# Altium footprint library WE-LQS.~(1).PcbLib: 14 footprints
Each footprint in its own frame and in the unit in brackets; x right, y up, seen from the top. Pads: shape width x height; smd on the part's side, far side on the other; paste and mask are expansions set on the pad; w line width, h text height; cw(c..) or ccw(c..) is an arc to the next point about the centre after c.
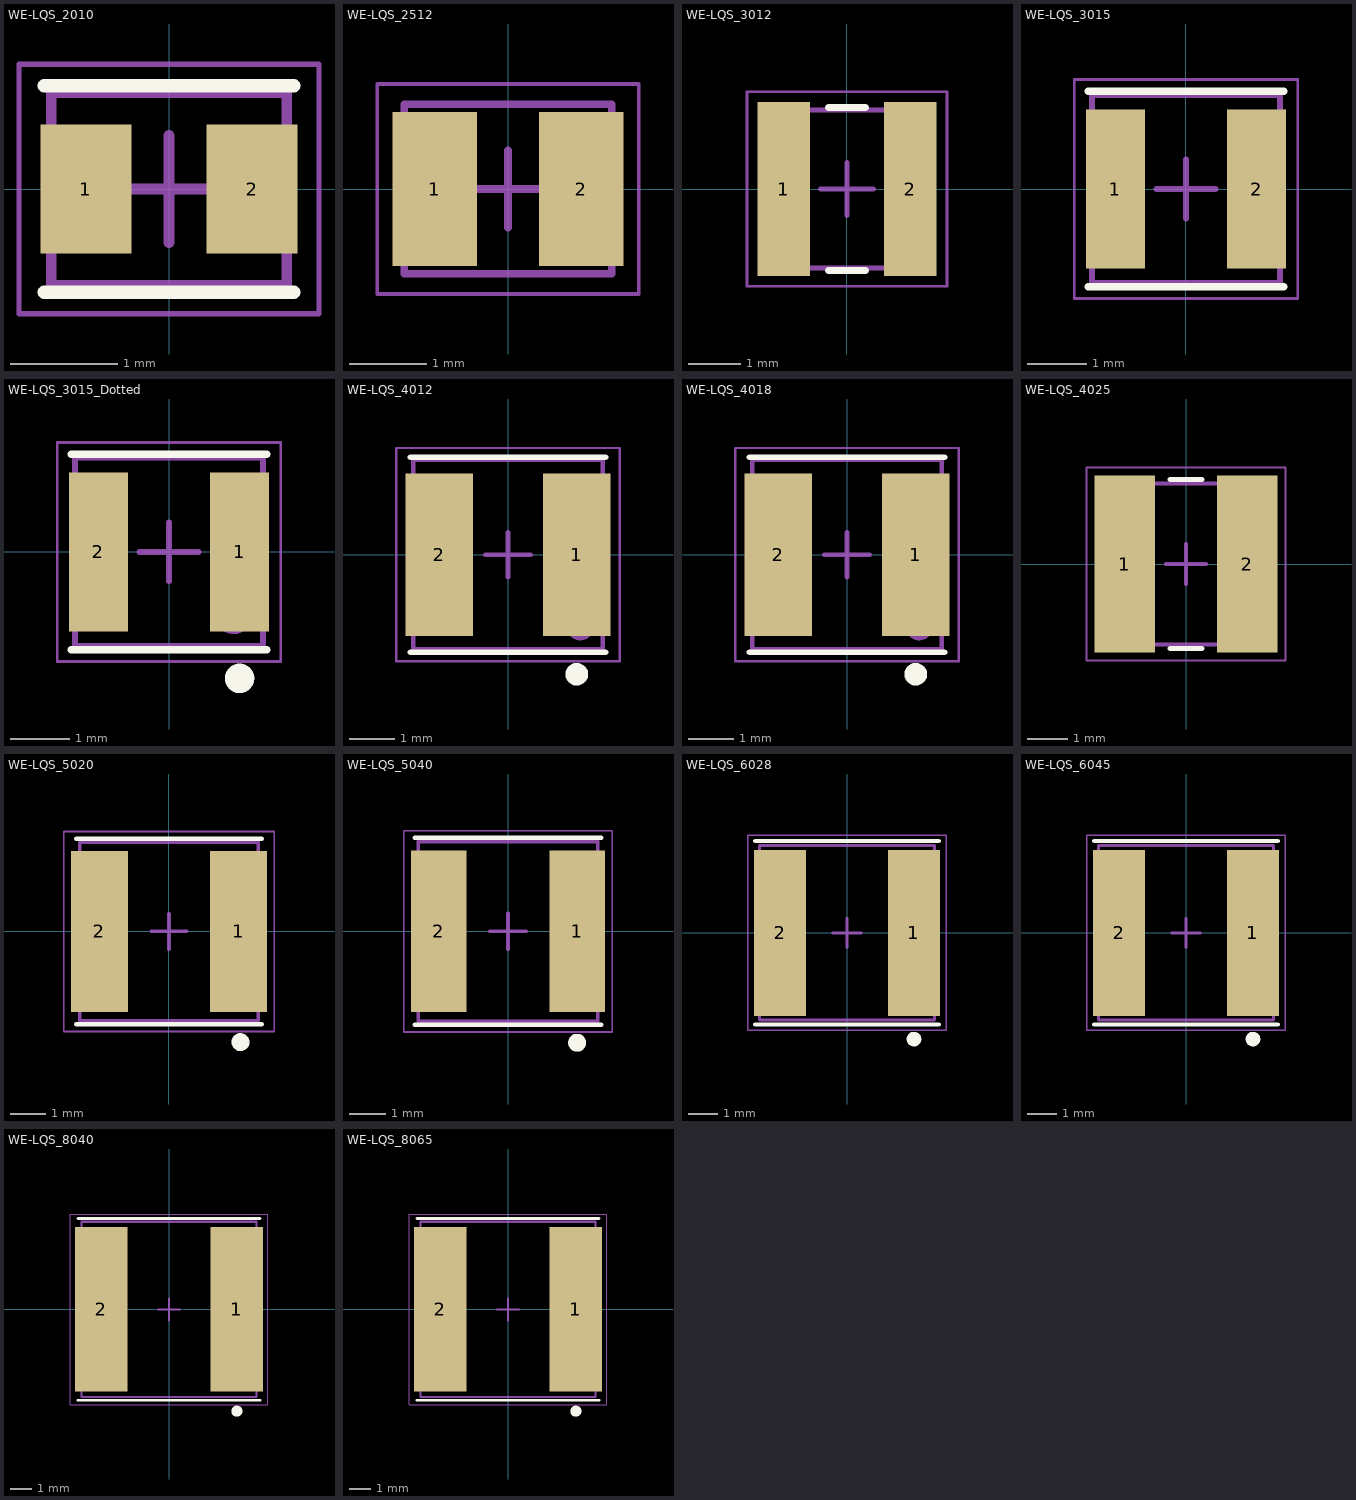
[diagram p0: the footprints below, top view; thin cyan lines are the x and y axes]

## WE-LQS_2010 [mm] "SMD Power Inductor, 2-Leads, body 2x1.6mm"
height 1
pads (2):
  rect 0.85x1.2 smd: 1(-0.775,0) 2(0.775,0)
Top Overlay:
  lines w0.127: -1.164,-0.964 1.164,-0.964 ; -1.164,0.964 1.164,0.964
Top Assembly:
  lines w0.1: -1.1,-0.9 1.1,-0.9 1.1,0.9 -1.1,0.9 -1.1,-0.9
Top Designator:
  text ".Designator" at -3.647,-0.357 h1
Top Courtyard:
  lines w0.05: -1.4,-1.164 1.4,-1.164 1.4,1.164 -1.4,1.164 -1.4,-1.164
Top Component Center:
  lines w0.1: -0.5,0 0.5,0 ; 0,-0.5 0,0.5
3D body "IndLQS_2010.stp": height 1.01, standoff 0.01, extent -1,-0.8 1,0.824

## WE-LQS_2512 [mm] "SMD Power Inductor, 2-Leads, body 2.5x2mm"
height 1.2
pads (2):
  rect 1.1x2 smd: 1(-0.95,0) 2(0.95,0)
Top Assembly:
  lines w0.1: -1.35,-1.1 -1.35,1.1 1.35,1.1 1.35,-1.1 -1.35,-1.1
Top Designator:
  text ".Designator" at -3.647,-0.357 h1
Top Courtyard:
  lines w0.05: -1.7,-1.363 1.7,-1.363 1.7,1.363 -1.7,1.363 -1.7,-1.363
Top Component Center:
  lines w0.1: -0.5,0 0.5,0 ; 0,-0.5 0,0.5
3D body "IndLQS_2512.stp": height 1.2, standoff 0, extent -1.25,-1 1.25,1

## WE-LQS_3012 [mm] "SMD Power Inductor, 2-Leads, body 3x3mm"
height 1.2
pads (2):
  rect 1x3.3 smd: 1(-1.2,0) 2(1.2,0)
Top Overlay:
  lines w0.127: -0.35,-1.55 0.35,-1.55 ; -0.35,1.55 0.35,1.55
Top Assembly:
  lines w0.1: -1.5,-1.5 1.5,-1.5 1.5,1.5 -1.5,1.5 -1.5,-1.5
Top Designator:
  text ".Designator" at -3.647,-0.357 h1
Top Courtyard:
  lines w0.05: -1.9,-1.85 -1.9,1.85 1.9,1.85 1.9,-1.85 -1.9,-1.85
Top Component Center:
  lines w0.1: -0.5,0 0.5,0 ; 0,-0.5 0,0.5
3D body "IndLQS_3012_TPI_74404031xxxA.stp": height 1.2, standoff 0, extent -1.5,-1.5 1.5,1.5

## WE-LQS_3015 [mm] "SMD Power Inductor, 2-Leads, body 3x3mm"
height 1.5
pads (2):
  rect 1x2.7 smd: 1(-1.2,0) 2(1.2,0)
Top Overlay:
  lines w0.127: -1.663,-1.663 1.663,-1.663 ; -1.663,1.663 1.663,1.663
Top Assembly:
  lines w0.1: -1.6,-1.6 1.6,-1.6 1.6,1.6 -1.6,1.6 -1.6,-1.6
Top Designator:
  text ".Designator" at -3.647,-0.357 h1
Top Courtyard:
  lines w0.05: -1.9,-1.863 -1.9,1.863 1.9,1.863 1.9,-1.863 -1.9,-1.863
Top Component Center:
  lines w0.1: -0.5,0 0.5,0 ; 0,-0.5 0,0.5
3D body "LQS_3015.stp": height 1.5, standoff 0, extent -1.5,-1.5 1.5,1.5

## WE-LQS_3015_Dotted [mm] "SMD Power Inductor, 2-Leads, body 3x3mm"
height 1.5
pads (2):
  rect 1x2.7 smd: 1(1.2,0) 2(-1.2,0)
Top Overlay:
  circle w0.25: c1.2,-2.15 r0.125
  lines w0.127: -1.663,-1.663 1.663,-1.663 ; -1.663,1.663 1.663,1.663
Top Assembly:
  circle w0.1: c1.1,-1.1 r0.25
  lines w0.1: -1.6,-1.6 -1.6,1.6 1.6,1.6 1.6,-1.6 -1.6,-1.6
Top Designator:
  text ".Designator" at -3.647,-0.357 h1
Top Courtyard:
  lines w0.05: -1.9,-1.863 1.9,-1.863 1.9,1.863 -1.9,1.863 -1.9,-1.863
Top Component Center:
  lines w0.1: -0.5,0 0.5,0 ; 0,-0.5 0,0.5
3D body "IndLQS_3015_74404032220.stp": height 1.45, standoff -0.01, extent -1.5,-1.5 1.5,1.5

## WE-LQS_4012 [mm] "SMD Power Inductor, 2-Leads, body 4x4mm"
height 1.2
pads (2):
  rect 1.5x3.6 smd: 1(1.525,0) 2(-1.525,0)
Top Overlay:
  circle w0.25: c1.525,-2.65 r0.125
  lines w0.127: -2.164,-2.164 2.164,-2.164 ; -2.164,2.164 2.164,2.164
Top Assembly:
  circle w0.1: c1.6,-1.6 r0.25
  lines w0.1: -2.1,-2.1 2.1,-2.1 2.1,2.1 -2.1,2.1 -2.1,-2.1
Top Designator:
  text ".Designator" at -3.647,-0.357 h1
Top Courtyard:
  lines w0.05: -2.475,-2.364 -2.475,2.364 2.475,2.364 2.475,-2.364 -2.475,-2.364
Top Component Center:
  lines w0.1: -0.5,0 0.5,0 ; 0,-0.5 0,0.5
3D body "IndLQS_4012.stp": height 1.19, standoff -0.01, extent -2,-2 2,2

## WE-LQS_4018 [mm] "SMD Power Inductor, 2-Leads, body 4x4mm"
height 1.8
pads (2):
  rect 1.5x3.6 smd: 1(1.525,0) 2(-1.525,0)
Top Overlay:
  circle w0.25: c1.525,-2.65 r0.125
  lines w0.127: -2.164,-2.164 2.164,-2.164 ; -2.164,2.164 2.164,2.164
Top Assembly:
  circle w0.1: c1.6,-1.6 r0.25
  lines w0.1: -2.1,-2.1 2.1,-2.1 2.1,2.1 -2.1,2.1 -2.1,-2.1
Top Designator:
  text ".Designator" at -3.647,-0.357 h1
Top Courtyard:
  lines w0.05: -2.475,-2.364 -2.475,2.364 2.475,2.364 2.475,-2.364 -2.475,-2.364
Top Component Center:
  lines w0.1: -0.5,0 0.5,0 ; 0,-0.5 0,0.5
3D body "IndLQS_4018.stp": height 1.8, standoff 0, extent -2,-2 2,2

## WE-LQS_4025 [mm] "SMD Power Inductor, 2-Leads, body 4x4mm"
height 2.5
pads (2):
  rect 1.5x4.4 smd: 1(-1.525,0) 2(1.525,0)
Top Overlay:
  lines w0.127: -0.4,-2.1 0.4,-2.1 ; -0.4,2.1 0.4,2.1
Top Assembly:
  lines w0.1: -2,-2 -2,2 2,2 2,-2 -2,-2
Top Designator:
  text ".Designator" at -3.647,-0.357 h1
Top 3D Body:
  lines w0.1: -2,-2 -2,2 2,2 2,-2 -2,-2
Top Courtyard:
  lines w0.05: -2.475,-2.4 2.475,-2.4 2.475,2.4 -2.475,2.4 -2.475,-2.4
Top Component Center:
  lines w0.1: -0.5,0 0.5,0 ; 0,-0.5 0,0.5
3D body "IndLQS_4025_74404043xxxA.stp": height 2.15, standoff 0, extent -2,-2 2,2

## WE-LQS_5020 [mm] "SMD Power Inductor, 2-Leads, body 5x5mm"
height 2
pads (2):
  rect 1.6x4.5 smd: 1(1.95,0) 2(-1.95,0)
Top Overlay:
  circle w0.25: c2,-3.1 r0.125
  lines w0.127: -2.6,-2.6 2.6,-2.6 ; -2.6,2.6 2.6,2.6
Top Assembly:
  circle w0.1: c1.7,-1.7 r0.3
  lines w0.1: -2.5,-2.5 2.5,-2.5 2.5,2.5 -2.5,2.5 -2.5,-2.5
Top Designator:
  text ".Designator" at -3.647,-0.357 h1
Top 3D Body:
  circle w0.1: c1.7,-1.7 r0.3
  lines w0.1: -2.5,-2.5 2.5,-2.5 2.5,2.5 -2.5,2.5 -2.5,-2.5
Top Courtyard:
  lines w0.05: -2.95,-2.8 -2.95,2.8 2.95,2.8 2.95,-2.8 -2.95,-2.8
Top Component Center:
  lines w0.1: -0.5,0 0.5,0 ; 0,-0.5 0,0.5
3D body "IndLQS_5020S.stp": height 2, standoff 0, extent -2.5,-2.5 2.5,2.5

## WE-LQS_5040 [mm] "SMD Power Inductor, 2-Leads, body 5x5mm"
height 4
pads (2):
  rect 1.55x4.5 smd: 1(1.925,0) 2(-1.925,0)
Top Overlay:
  circle w0.25: c1.925,-3.1 r0.125
  lines w0.127: -2.6,-2.6 2.6,-2.6 ; -2.6,2.6 2.6,2.6
Top Assembly:
  circle w0.1: c1.7,-1.7 r0.3
  lines w0.1: -2.5,-2.5 2.5,-2.5 2.5,2.5 -2.5,2.5 -2.5,-2.5
Top Designator:
  text ".Designator" at -3.647,-0.357 h1
Top 3D Body:
  circle w0.1: c1.7,-1.7 r0.3
  lines w0.1: -2.5,-2.5 2.5,-2.5 2.5,2.5 -2.5,2.5 -2.5,-2.5
Top Courtyard:
  lines w0.05: -2.9,-2.8 2.9,-2.8 2.9,2.8 -2.9,2.8 -2.9,-2.8
Top Component Center:
  lines w0.1: -0.5,0 0.5,0 ; 0,-0.5 0,0.5
3D body "LQS_5040.stp": height 4.03, standoff 0.03, extent -2.5,-2.5 2.5,2.5

## WE-LQS_6028 [mm] "SMD Power Inductor, 2-Leads, body 6x6mm"
height 2.8
pads (2):
  rect 1.8x5.7 smd: 1(2.3,0) 2(-2.3,0)
Top Overlay:
  circle w0.25: c2.3,-3.65 r0.125
  lines w0.15: -3.15,-3.15 3.15,-3.15 ; -3.15,3.15 3.15,3.15
Top Assembly:
  circle w0.1: c2.2,-2.2 r0.3
  lines w0.1: -3,-3 3,-3 3,3 -3,3 -3,-3
Top Designator:
  text ".Designator" at -3.647,-0.357 h1
Top 3D Body:
  circle w0.1: c2.2,-2.2 r0.3
  lines w0.1: -3,-3 3,-3 3,3 -3,3 -3,-3
Top Courtyard:
  lines w0.05: -3.4,-3.35 3.4,-3.35 3.4,3.35 -3.4,3.35 -3.4,-3.35
Top Component Center:
  lines w0.1: -0.5,0 0.5,0 ; 0,-0.5 0,0.5
3D body "LQS_6028.stp": height 2.83, standoff 0.02, extent -3,-3 3,3

## WE-LQS_6045 [mm] "SMD Power Inductor, 2-Leads, body 6x6mm"
height 4.5
pads (2):
  rect 1.8x5.7 smd: 1(2.3,0) 2(-2.3,0)
Top Overlay:
  circle w0.25: c2.3,-3.65 r0.125
  lines w0.15: -3.15,-3.15 3.15,-3.15 ; -3.15,3.15 3.15,3.15
Top Assembly:
  circle w0.1: c2.2,-2.2 r0.3
  lines w0.1: -3,-3 3,-3 3,3 -3,3 -3,-3
Top Designator:
  text ".Designator" at -3.647,-0.357 h1
Top 3D Body:
  circle w0.1: c2.2,-2.2 r0.3
  lines w0.1: -3,-3 3,-3 3,3 -3,3 -3,-3
Top Courtyard:
  lines w0.05: -3.4,-3.35 3.4,-3.35 3.4,3.35 -3.4,3.35 -3.4,-3.35
Top Component Center:
  lines w0.1: -0.5,0 0.5,0 ; 0,-0.5 0,0.5
3D body "LQS_6045.stp": height 4.52, standoff 0.02, extent -3,-3 3,3

## WE-LQS_8040 [mm] "SMD Power Inductor, 2-Leads, body 8x8mm"
height 4.2
pads (2):
  rect 2.4x7.5 smd: 1(3.1,0) 2(-3.1,0)
Top Overlay:
  circle w0.25: c3.1,-4.65 r0.125
  lines w0.127: -4.15,-4.15 4.15,-4.15 ; -4.15,4.15 4.15,4.15
Top Assembly:
  circle w0.1: c3,-3 r0.4
  lines w0.1: -4,-4 4,-4 4,4 -4,4 -4,-4
Top Designator:
  text ".Designator" at -3.647,-0.357 h1
Top 3D Body:
  circle w0.1: c3,-3 r0.4
  lines w0.1: -4,-4 4,-4 4,4 -4,4 -4,-4
Top Courtyard:
  lines w0.05: -4.5,-4.35 -4.5,4.35 4.5,4.35 4.5,-4.35 -4.5,-4.35
Top Component Center:
  lines w0.1: -0.5,0 0.5,0 ; 0,-0.5 0,0.5
3D body "LQS_8040.stp": height 4.2, standoff 0, extent -4,-4 4,4

## WE-LQS_8065 [mm] "SMD Power Inductor, 2-Leads, body 8.3x8.3mm"
height 6.5
pads (2):
  rect 2.4x7.5 smd: 1(3.1,0) 2(-3.1,0)
Top Overlay:
  circle w0.25: c3.1,-4.65 r0.125
  lines w0.127: -4.15,-4.15 4.15,-4.15 ; -4.15,4.15 4.15,4.15
Top Assembly:
  circle w0.1: c3,-3 r0.4
  lines w0.1: -4,-4 -4,4 4,4 4,-4 -4,-4
Top Designator:
  text ".Designator" at -3.647,-0.357 h1
Top 3D Body:
  circle w0.1: c3,-3 r0.4
  lines w0.1: -4,-4 -4,4 4,4 4,-4 -4,-4
Top Courtyard:
  lines w0.05: -4.5,-4.35 4.5,-4.35 4.5,4.35 -4.5,4.35 -4.5,-4.35
Top Component Center:
  lines w0.1: -0.5,0 0.5,0 ; 0,-0.5 0,0.5
3D body "IndLQS_8065.stp": height 6.52, standoff 0.02, extent -4,-4 4,4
